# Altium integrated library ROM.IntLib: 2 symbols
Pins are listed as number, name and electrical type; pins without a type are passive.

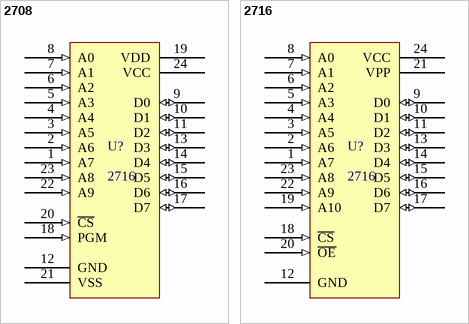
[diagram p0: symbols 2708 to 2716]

## 2708
designator U?, comment 2716
footprint DIP24M (2.5mm grid)
pins: 1 A7 (in), 2 A6 (in), 3 A5 (in), 4 A4 (in), 5 A3 (in), 6 A2 (in), 7 A1 (in), 8 A0 (in), 9 D0 (io), 10 D1 (io), 11 D2 (io), 12 GND (power), 13 D3 (io), 14 D4 (io), 15 D5 (io), 16 D6 (io), 17 D7 (io), 18 PGM (in), 19 VDD (power), 20 ~{CS} (in), 21 VSS (power), 22 A9 (in), 23 A8 (in), 24 VCC (power)

## 2716
designator U?
footprint DIP24M (2.5mm grid)
pins: 1 A7 (in), 2 A6 (in), 3 A5 (in), 4 A4 (in), 5 A3 (in), 6 A2 (in), 7 A1 (in), 8 A0 (in), 9 D0 (io), 10 D1 (io), 11 D2 (io), 12 GND (power), 13 D3 (io), 14 D4 (io), 15 D5 (io), 16 D6 (io), 17 D7 (io), 18 ~{CS} (in), 19 A10 (in), 20 ~{OE} (in), 21 VPP (power), 22 A9 (in), 23 A8 (in), 24 VCC (power)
